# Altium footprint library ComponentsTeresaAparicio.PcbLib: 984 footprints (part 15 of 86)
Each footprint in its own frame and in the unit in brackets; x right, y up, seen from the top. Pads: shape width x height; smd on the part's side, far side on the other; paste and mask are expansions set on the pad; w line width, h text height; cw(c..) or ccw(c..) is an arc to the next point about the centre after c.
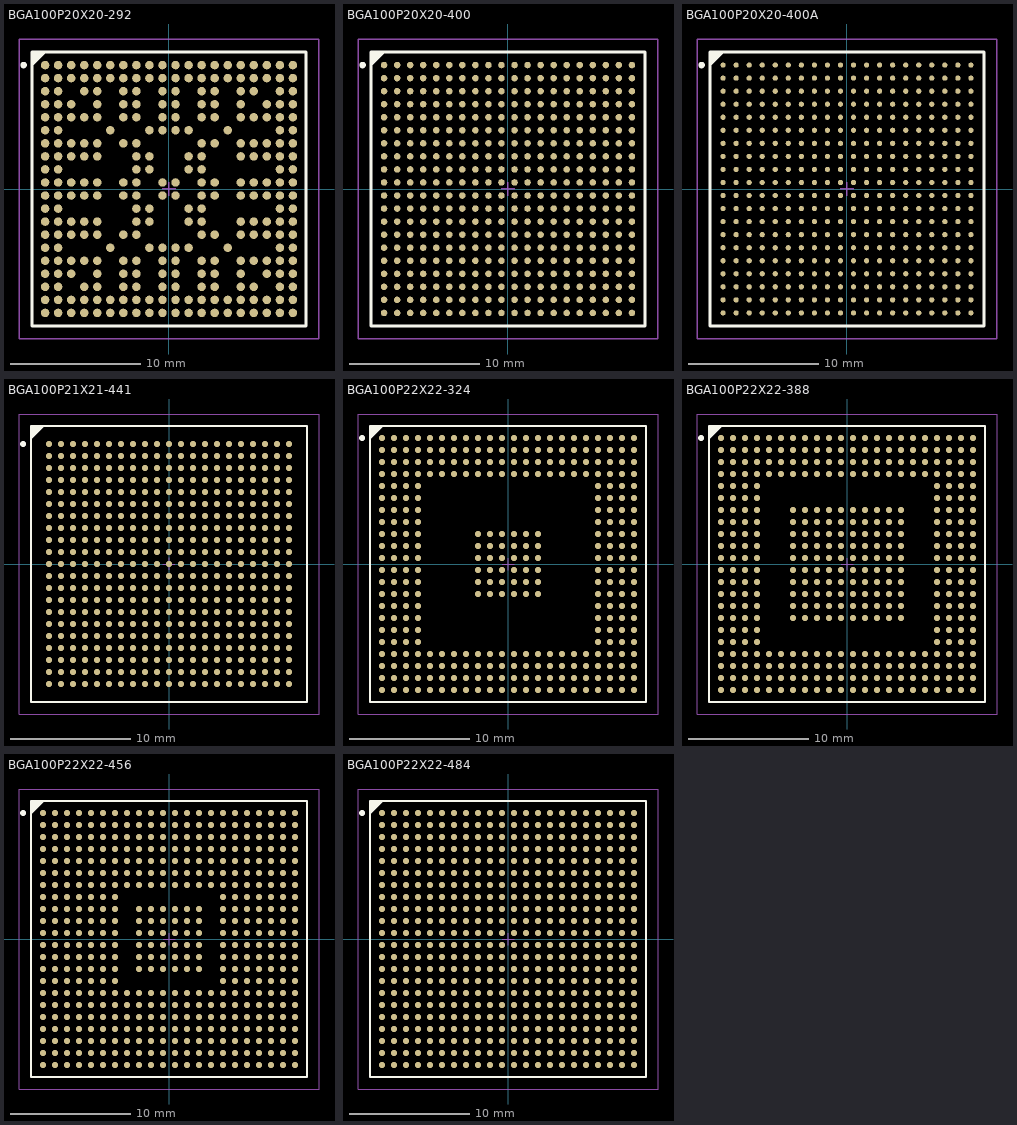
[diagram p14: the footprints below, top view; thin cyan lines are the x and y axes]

## BGA100P20X20-292 [mm] "BGA, 292-Leads, Body 21x21mm, Pitch 1mm"
height 3.09
pads (292):
  round 0.65 smd: A1(-9.5,9.5) A2(-8.5,9.5) A3(-7.5,9.5) A4(-6.5,9.5) A5(-5.5,9.5) A6(-4.5,9.5) A7(-3.5,9.5) A8(-2.5,9.5) A9(-1.5,9.5) A10(-0.5,9.5) A11(0.5,9.5) A12(1.5,9.5) A13(2.5,9.5) A14(3.5,9.5) A15(4.5,9.5) A16(5.5,9.5) A17(6.5,9.5) A18(7.5,9.5) A19(8.5,9.5) A20(9.5,9.5) B1(-9.5,8.5) B2(-8.5,8.5) B3(-7.5,8.5) B4(-6.5,8.5) B5(-5.5,8.5) B6(-4.5,8.5) B7(-3.5,8.5) B8(-2.5,8.5) B9(-1.5,8.5) B10(-0.5,8.5) B11(0.5,8.5) B12(1.5,8.5) B13(2.5,8.5) B14(3.5,8.5) B15(4.5,8.5) B16(5.5,8.5) B17(6.5,8.5) B18(7.5,8.5) B19(8.5,8.5) B20(9.5,8.5) C1(-9.5,7.5) C2(-8.5,7.5) C4(-6.5,7.5) C5(-5.5,7.5) C7(-3.5,7.5) C8(-2.5,7.5) C10(-0.5,7.5) C11(0.5,7.5) C13(2.5,7.5) C14(3.5,7.5) C16(5.5,7.5) C17(6.5,7.5) C19(8.5,7.5) C20(9.5,7.5) D1(-9.5,6.5) D2(-8.5,6.5) D3(-7.5,6.5) D5(-5.5,6.5) D7(-3.5,6.5) D8(-2.5,6.5) D10(-0.5,6.5) D11(0.5,6.5) D13(2.5,6.5) D14(3.5,6.5) D16(5.5,6.5) D18(7.5,6.5) D19(8.5,6.5) D20(9.5,6.5) E1(-9.5,5.5) E2(-8.5,5.5) E3(-7.5,5.5) E4(-6.5,5.5) E5(-5.5,5.5) E7(-3.5,5.5) E8(-2.5,5.5) E10(-0.5,5.5) E11(0.5,5.5) E13(2.5,5.5) E14(3.5,5.5) E16(5.5,5.5) E17(6.5,5.5) E18(7.5,5.5) E19(8.5,5.5) E20(9.5,5.5) F1(-9.5,4.5) F2(-8.5,4.5) F6(-4.5,4.5) F9(-1.5,4.5) F10(-0.5,4.5) F11(0.5,4.5) F12(1.5,4.5) F15(4.5,4.5) F19(8.5,4.5) F20(9.5,4.5) G1(-9.5,3.5) G2(-8.5,3.5) G3(-7.5,3.5) G4(-6.5,3.5) G5(-5.5,3.5) G7(-3.5,3.5) G8(-2.5,3.5) G13(2.5,3.5) G14(3.5,3.5) G16(5.5,3.5) G17(6.5,3.5) G18(7.5,3.5) G19(8.5,3.5) G20(9.5,3.5) H1(-9.5,2.5) H2(-8.5,2.5) H3(-7.5,2.5) H4(-6.5,2.5) H5(-5.5,2.5) H8(-2.5,2.5) H9(-1.5,2.5) H12(1.5,2.5) H13(2.5,2.5) H16(5.5,2.5) H17(6.5,2.5) H18(7.5,2.5) H19(8.5,2.5) H20(9.5,2.5) J1(-9.5,1.5) J2(-8.5,1.5) J8(-2.5,1.5) J9(-1.5,1.5) J12(1.5,1.5) J13(2.5,1.5) J19(8.5,1.5) J20(9.5,1.5) K1(-9.5,0.5) K2(-8.5,0.5) K3(-7.5,0.5) K4(-6.5,0.5) K5(-5.5,0.5) K7(-3.5,0.5) K8(-2.5,0.5) K10(-0.5,0.5) K11(0.5,0.5) K13(2.5,0.5) K14(3.5,0.5) K16(5.5,0.5) K17(6.5,0.5) K18(7.5,0.5) K19(8.5,0.5) K20(9.5,0.5) L1(-9.5,-0.5) L2(-8.5,-0.5) L3(-7.5,-0.5) L4(-6.5,-0.5) L5(-5.5,-0.5) L7(-3.5,-0.5) L8(-2.5,-0.5) L10(-0.5,-0.5) L11(0.5,-0.5) L13(2.5,-0.5) L14(3.5,-0.5) L16(5.5,-0.5) L17(6.5,-0.5) L18(7.5,-0.5) L19(8.5,-0.5) L20(9.5,-0.5) M1(-9.5,-1.5) M2(-8.5,-1.5) M8(-2.5,-1.5) M9(-1.5,-1.5) M12(1.5,-1.5) M13(2.5,-1.5) M19(8.5,-1.5) M20(9.5,-1.5) N1(-9.5,-2.5) N2(-8.5,-2.5) N3(-7.5,-2.5) N4(-6.5,-2.5) N5(-5.5,-2.5) N8(-2.5,-2.5) N9(-1.5,-2.5) N12(1.5,-2.5) N13(2.5,-2.5) N16(5.5,-2.5) N17(6.5,-2.5) N18(7.5,-2.5) N19(8.5,-2.5) N20(9.5,-2.5) P1(-9.5,-3.5) P2(-8.5,-3.5) P3(-7.5,-3.5) P4(-6.5,-3.5) P5(-5.5,-3.5) P7(-3.5,-3.5) P8(-2.5,-3.5) P13(2.5,-3.5) P14(3.5,-3.5) P16(5.5,-3.5) P17(6.5,-3.5) P18(7.5,-3.5) P19(8.5,-3.5) P20(9.5,-3.5) R1(-9.5,-4.5) R2(-8.5,-4.5) R6(-4.5,-4.5) R9(-1.5,-4.5) R10(-0.5,-4.5) R11(0.5,-4.5) R12(1.5,-4.5) R15(4.5,-4.5) R19(8.5,-4.5) R20(9.5,-4.5) T1(-9.5,-5.5) T2(-8.5,-5.5) T3(-7.5,-5.5) T4(-6.5,-5.5) T5(-5.5,-5.5) T7(-3.5,-5.5) T8(-2.5,-5.5) T10(-0.5,-5.5) T11(0.5,-5.5) T13(2.5,-5.5) T14(3.5,-5.5) T16(5.5,-5.5) T17(6.5,-5.5) T18(7.5,-5.5) T19(8.5,-5.5) T20(9.5,-5.5) U1(-9.5,-6.5) U2(-8.5,-6.5) U3(-7.5,-6.5) U5(-5.5,-6.5) U7(-3.5,-6.5) U8(-2.5,-6.5) U10(-0.5,-6.5) U11(0.5,-6.5) U13(2.5,-6.5) U14(3.5,-6.5) U16(5.5,-6.5) U18(7.5,-6.5) U19(8.5,-6.5) U20(9.5,-6.5) V1(-9.5,-7.5) V2(-8.5,-7.5) V4(-6.5,-7.5) V5(-5.5,-7.5) V7(-3.5,-7.5) V8(-2.5,-7.5) V10(-0.5,-7.5) V11(0.5,-7.5) V13(2.5,-7.5) V14(3.5,-7.5) V16(5.5,-7.5) V17(6.5,-7.5) V19(8.5,-7.5) V20(9.5,-7.5) W1(-9.5,-8.5) W2(-8.5,-8.5) W3(-7.5,-8.5) W4(-6.5,-8.5) W5(-5.5,-8.5) W6(-4.5,-8.5) W7(-3.5,-8.5) W8(-2.5,-8.5) W9(-1.5,-8.5) W10(-0.5,-8.5) W11(0.5,-8.5) W12(1.5,-8.5) W13(2.5,-8.5) W14(3.5,-8.5) W15(4.5,-8.5) W16(5.5,-8.5) W17(6.5,-8.5) W18(7.5,-8.5) W19(8.5,-8.5) W20(9.5,-8.5) Y1(-9.5,-9.5) Y2(-8.5,-9.5) Y3(-7.5,-9.5) Y4(-6.5,-9.5) Y5(-5.5,-9.5) Y6(-4.5,-9.5) Y7(-3.5,-9.5) Y8(-2.5,-9.5) Y9(-1.5,-9.5) Y10(-0.5,-9.5) Y11(0.5,-9.5) Y12(1.5,-9.5) Y13(2.5,-9.5) Y14(3.5,-9.5) Y15(4.5,-9.5) Y16(5.5,-9.5) Y17(6.5,-9.5) Y18(7.5,-9.5) Y19(8.5,-9.5) Y20(9.5,-9.5)
Top Overlay:
  circle w0.25: c-11.15,9.5 r0.125
  region: -9.525,10.5 -10.5,9.525 -10.5,10.5
  lines w0.2: -10.5,9.525 -9.525,10.5 ; -10.5,-10.5 10.5,-10.5 10.5,10.5 -10.5,10.5 -10.5,-10.5
Mechanical 13:
  lines w0.1: -10.5,-10.5 10.5,-10.5 10.5,10.5 -10.5,10.5 -10.5,-10.5
Mechanical 15:
  lines w0.1: -0.5,0 0.5,0 ; 0,-0.5 0,0.5 ; -11.5,-11.5 11.5,-11.5 11.5,11.5 -11.5,11.5 -11.5,-11.5
3D body: height 0, standoff 0, extent -10.5,-10.5 10.5,10.5

## BGA100P20X20-400 [mm] "BGA, 400-Leads, Body 21x21mm, Pitch 1mm"
height 2.2
pads (400):
  round 0.5 smd: A1(-9.5,9.5) A2(-8.5,9.5) A3(-7.5,9.5) A4(-6.5,9.5) A5(-5.5,9.5) A6(-4.5,9.5) A7(-3.5,9.5) A8(-2.5,9.5) A9(-1.5,9.5) A10(-0.5,9.5) A11(0.5,9.5) A12(1.5,9.5) A13(2.5,9.5) A14(3.5,9.5) A15(4.5,9.5) A16(5.5,9.5) A17(6.5,9.5) A18(7.5,9.5) A19(8.5,9.5) A20(9.5,9.5) B1(-9.5,8.5) B2(-8.5,8.5) B3(-7.5,8.5) B4(-6.5,8.5) B5(-5.5,8.5) B6(-4.5,8.5) B7(-3.5,8.5) B8(-2.5,8.5) B9(-1.5,8.5) B10(-0.5,8.5) B11(0.5,8.5) B12(1.5,8.5) B13(2.5,8.5) B14(3.5,8.5) B15(4.5,8.5) B16(5.5,8.5) B17(6.5,8.5) B18(7.5,8.5) B19(8.5,8.5) B20(9.5,8.5) C1(-9.5,7.5) C2(-8.5,7.5) C3(-7.5,7.5) C4(-6.5,7.5) C5(-5.5,7.5) C6(-4.5,7.5) C7(-3.5,7.5) C8(-2.5,7.5) C9(-1.5,7.5) C10(-0.5,7.5) C11(0.5,7.5) C12(1.5,7.5) C13(2.5,7.5) C14(3.5,7.5) C15(4.5,7.5) C16(5.5,7.5) C17(6.5,7.5) C18(7.5,7.5) C19(8.5,7.5) C20(9.5,7.5) D1(-9.5,6.5) D2(-8.5,6.5) D3(-7.5,6.5) D4(-6.5,6.5) D5(-5.5,6.5) D6(-4.5,6.5) D7(-3.5,6.5) D8(-2.5,6.5) D9(-1.5,6.5) D10(-0.5,6.5) D11(0.5,6.5) D12(1.5,6.5) D13(2.5,6.5) D14(3.5,6.5) D15(4.5,6.5) D16(5.5,6.5) D17(6.5,6.5) D18(7.5,6.5) D19(8.5,6.5) D20(9.5,6.5) E1(-9.5,5.5) E2(-8.5,5.5) E3(-7.5,5.5) E4(-6.5,5.5) E5(-5.5,5.5) E6(-4.5,5.5) E7(-3.5,5.5) E8(-2.5,5.5) E9(-1.5,5.5) E10(-0.5,5.5) E11(0.5,5.5) E12(1.5,5.5) E13(2.5,5.5) E14(3.5,5.5) E15(4.5,5.5) E16(5.5,5.5) E17(6.5,5.5) E18(7.5,5.5) E19(8.5,5.5) E20(9.5,5.5) F1(-9.5,4.5) F2(-8.5,4.5) F3(-7.5,4.5) F4(-6.5,4.5) F5(-5.5,4.5) F6(-4.5,4.5) F7(-3.5,4.5) F8(-2.5,4.5) F9(-1.5,4.5) F10(-0.5,4.5) F11(0.5,4.5) F12(1.5,4.5) F13(2.5,4.5) F14(3.5,4.5) F15(4.5,4.5) F16(5.5,4.5) F17(6.5,4.5) F18(7.5,4.5) F19(8.5,4.5) F20(9.5,4.5) G1(-9.5,3.5) G2(-8.5,3.5) G3(-7.5,3.5) G4(-6.5,3.5) G5(-5.5,3.5) G6(-4.5,3.5) G7(-3.5,3.5) G8(-2.5,3.5) G9(-1.5,3.5) G10(-0.5,3.5) G11(0.5,3.5) G12(1.5,3.5) G13(2.5,3.5) G14(3.5,3.5) G15(4.5,3.5) G16(5.5,3.5) G17(6.5,3.5) G18(7.5,3.5) G19(8.5,3.5) G20(9.5,3.5) H1(-9.5,2.5) H2(-8.5,2.5) H3(-7.5,2.5) H4(-6.5,2.5) H5(-5.5,2.5) H6(-4.5,2.5) H7(-3.5,2.5) H8(-2.5,2.5) H9(-1.5,2.5) H10(-0.5,2.5) H11(0.5,2.5) H12(1.5,2.5) H13(2.5,2.5) H14(3.5,2.5) H15(4.5,2.5) H16(5.5,2.5) H17(6.5,2.5) H18(7.5,2.5) H19(8.5,2.5) H20(9.5,2.5) J1(-9.5,1.5) J2(-8.5,1.5) J3(-7.5,1.5) J4(-6.5,1.5) J5(-5.5,1.5) J6(-4.5,1.5) J7(-3.5,1.5) J8(-2.5,1.5) J9(-1.5,1.5) J10(-0.5,1.5) J11(0.5,1.5) J12(1.5,1.5) J13(2.5,1.5) J14(3.5,1.5) J15(4.5,1.5) J16(5.5,1.5) J17(6.5,1.5) J18(7.5,1.5) J19(8.5,1.5) J20(9.5,1.5) K1(-9.5,0.5) K2(-8.5,0.5) K3(-7.5,0.5) K4(-6.5,0.5) K5(-5.5,0.5) K6(-4.5,0.5) K7(-3.5,0.5) K8(-2.5,0.5) K9(-1.5,0.5) K10(-0.5,0.5) K11(0.5,0.5) K12(1.5,0.5) K13(2.5,0.5) K14(3.5,0.5) K15(4.5,0.5) K16(5.5,0.5) K17(6.5,0.5) K18(7.5,0.5) K19(8.5,0.5) K20(9.5,0.5) L1(-9.5,-0.5) L2(-8.5,-0.5) L3(-7.5,-0.5) L4(-6.5,-0.5) L5(-5.5,-0.5) L6(-4.5,-0.5) L7(-3.5,-0.5) L8(-2.5,-0.5) L9(-1.5,-0.5) L10(-0.5,-0.5) L11(0.5,-0.5) L12(1.5,-0.5) L13(2.5,-0.5) L14(3.5,-0.5) L15(4.5,-0.5) L16(5.5,-0.5) L17(6.5,-0.5) L18(7.5,-0.5) L19(8.5,-0.5) L20(9.5,-0.5) M1(-9.5,-1.5) M2(-8.5,-1.5) M3(-7.5,-1.5) M4(-6.5,-1.5) M5(-5.5,-1.5) M6(-4.5,-1.5) M7(-3.5,-1.5) M8(-2.5,-1.5) M9(-1.5,-1.5) M10(-0.5,-1.5) M11(0.5,-1.5) M12(1.5,-1.5) M13(2.5,-1.5) M14(3.5,-1.5) M15(4.5,-1.5) M16(5.5,-1.5) M17(6.5,-1.5) M18(7.5,-1.5) M19(8.5,-1.5) M20(9.5,-1.5) N1(-9.5,-2.5) N2(-8.5,-2.5) N3(-7.5,-2.5) N4(-6.5,-2.5) N5(-5.5,-2.5) N6(-4.5,-2.5) N7(-3.5,-2.5) N8(-2.5,-2.5) N9(-1.5,-2.5) N10(-0.5,-2.5) N11(0.5,-2.5) N12(1.5,-2.5) N13(2.5,-2.5) N14(3.5,-2.5) N15(4.5,-2.5) N16(5.5,-2.5) N17(6.5,-2.5) N18(7.5,-2.5) N19(8.5,-2.5) N20(9.5,-2.5) P1(-9.5,-3.5) P2(-8.5,-3.5) P3(-7.5,-3.5) P4(-6.5,-3.5) P5(-5.5,-3.5) P6(-4.5,-3.5) P7(-3.5,-3.5) P8(-2.5,-3.5) P9(-1.5,-3.5) P10(-0.5,-3.5) P11(0.5,-3.5) P12(1.5,-3.5) P13(2.5,-3.5) P14(3.5,-3.5) P15(4.5,-3.5) P16(5.5,-3.5) P17(6.5,-3.5) P18(7.5,-3.5) P19(8.5,-3.5) P20(9.5,-3.5) R1(-9.5,-4.5) R2(-8.5,-4.5) R3(-7.5,-4.5) R4(-6.5,-4.5) R5(-5.5,-4.5) R6(-4.5,-4.5) R7(-3.5,-4.5) R8(-2.5,-4.5) R9(-1.5,-4.5) R10(-0.5,-4.5) R11(0.5,-4.5) R12(1.5,-4.5) R13(2.5,-4.5) R14(3.5,-4.5) R15(4.5,-4.5) R16(5.5,-4.5) R17(6.5,-4.5) R18(7.5,-4.5) R19(8.5,-4.5) R20(9.5,-4.5) T1(-9.5,-5.5) T2(-8.5,-5.5) T3(-7.5,-5.5) T4(-6.5,-5.5) T5(-5.5,-5.5) T6(-4.5,-5.5) T7(-3.5,-5.5) T8(-2.5,-5.5) T9(-1.5,-5.5) T10(-0.5,-5.5) T11(0.5,-5.5) T12(1.5,-5.5) T13(2.5,-5.5) T14(3.5,-5.5) T15(4.5,-5.5) T16(5.5,-5.5) T17(6.5,-5.5) T18(7.5,-5.5) T19(8.5,-5.5) T20(9.5,-5.5) U1(-9.5,-6.5) U2(-8.5,-6.5) U3(-7.5,-6.5) U4(-6.5,-6.5) U5(-5.5,-6.5) U6(-4.5,-6.5) U7(-3.5,-6.5) U8(-2.5,-6.5) U9(-1.5,-6.5) U10(-0.5,-6.5) U11(0.5,-6.5) U12(1.5,-6.5) U13(2.5,-6.5) U14(3.5,-6.5) U15(4.5,-6.5) U16(5.5,-6.5) U17(6.5,-6.5) U18(7.5,-6.5) U19(8.5,-6.5) U20(9.5,-6.5) V1(-9.5,-7.5) V2(-8.5,-7.5) V3(-7.5,-7.5) V4(-6.5,-7.5) V5(-5.5,-7.5) V6(-4.5,-7.5) V7(-3.5,-7.5) V8(-2.5,-7.5) V9(-1.5,-7.5) V10(-0.5,-7.5) V11(0.5,-7.5) V12(1.5,-7.5) V13(2.5,-7.5) V14(3.5,-7.5) V15(4.5,-7.5) V16(5.5,-7.5) V17(6.5,-7.5) V18(7.5,-7.5) V19(8.5,-7.5) V20(9.5,-7.5) W1(-9.5,-8.5) W2(-8.5,-8.5) W3(-7.5,-8.5) W4(-6.5,-8.5) W5(-5.5,-8.5) W6(-4.5,-8.5) W7(-3.5,-8.5) W8(-2.5,-8.5) W9(-1.5,-8.5) W10(-0.5,-8.5) W11(0.5,-8.5) W12(1.5,-8.5) W13(2.5,-8.5) W14(3.5,-8.5) W15(4.5,-8.5) W16(5.5,-8.5) W17(6.5,-8.5) W18(7.5,-8.5) W19(8.5,-8.5) W20(9.5,-8.5) Y1(-9.5,-9.5) Y2(-8.5,-9.5) Y3(-7.5,-9.5) Y4(-6.5,-9.5) Y5(-5.5,-9.5) Y6(-4.5,-9.5) Y7(-3.5,-9.5) Y8(-2.5,-9.5) Y9(-1.5,-9.5) Y10(-0.5,-9.5) Y11(0.5,-9.5) Y12(1.5,-9.5) Y13(2.5,-9.5) Y14(3.5,-9.5) Y15(4.5,-9.5) Y16(5.5,-9.5) Y17(6.5,-9.5) Y18(7.5,-9.5) Y19(8.5,-9.5) Y20(9.5,-9.5)
Top Overlay:
  circle w0.25: c-11.15,9.5 r0.125
  region: -9.5,10.5 -10.5,9.5 -10.5,10.5
  lines w0.2: -10.5,9.5 -9.5,10.5 ; -10.5,-10.5 -10.5,10.5 10.5,10.5 10.5,-10.5 -10.5,-10.5
Mechanical 13:
  lines w0.1: -10.5,-10.5 -10.5,10.5 10.5,10.5 10.5,-10.5 -10.5,-10.5
Mechanical 15:
  lines w0.1: -0.5,0 0.5,0 ; 0,-0.5 0,0.5 ; -11.5,-11.5 -11.5,11.5 11.5,11.5 11.5,-11.5 -11.5,-11.5
3D body: height 0, standoff 0, extent -10.5,-10.5 10.5,10.5

## BGA100P20X20-400A [mm] "BGA, 400-Leads, Body 21x21mm, Pitch 1mm"
height 1.4
pads (400):
  round 0.4 smd: A1(-9.5,9.5) A2(-8.5,9.5) A3(-7.5,9.5) A4(-6.5,9.5) A5(-5.5,9.5) A6(-4.5,9.5) A7(-3.5,9.5) A8(-2.5,9.5) A9(-1.5,9.5) A10(-0.5,9.5) A11(0.5,9.5) A12(1.5,9.5) A13(2.5,9.5) A14(3.5,9.5) A15(4.5,9.5) A16(5.5,9.5) A17(6.5,9.5) A18(7.5,9.5) A19(8.5,9.5) A20(9.5,9.5) B1(-9.5,8.5) B2(-8.5,8.5) B3(-7.5,8.5) B4(-6.5,8.5) B5(-5.5,8.5) B6(-4.5,8.5) B7(-3.5,8.5) B8(-2.5,8.5) B9(-1.5,8.5) B10(-0.5,8.5) B11(0.5,8.5) B12(1.5,8.5) B13(2.5,8.5) B14(3.5,8.5) B15(4.5,8.5) B16(5.5,8.5) B17(6.5,8.5) B18(7.5,8.5) B19(8.5,8.5) B20(9.5,8.5) C1(-9.5,7.5) C2(-8.5,7.5) C3(-7.5,7.5) C4(-6.5,7.5) C5(-5.5,7.5) C6(-4.5,7.5) C7(-3.5,7.5) C8(-2.5,7.5) C9(-1.5,7.5) C10(-0.5,7.5) C11(0.5,7.5) C12(1.5,7.5) C13(2.5,7.5) C14(3.5,7.5) C15(4.5,7.5) C16(5.5,7.5) C17(6.5,7.5) C18(7.5,7.5) C19(8.5,7.5) C20(9.5,7.5) D1(-9.5,6.5) D2(-8.5,6.5) D3(-7.5,6.5) D4(-6.5,6.5) D5(-5.5,6.5) D6(-4.5,6.5) D7(-3.5,6.5) D8(-2.5,6.5) D9(-1.5,6.5) D10(-0.5,6.5) D11(0.5,6.5) D12(1.5,6.5) D13(2.5,6.5) D14(3.5,6.5) D15(4.5,6.5) D16(5.5,6.5) D17(6.5,6.5) D18(7.5,6.5) D19(8.5,6.5) D20(9.5,6.5) E1(-9.5,5.5) E2(-8.5,5.5) E3(-7.5,5.5) E4(-6.5,5.5) E5(-5.5,5.5) E6(-4.5,5.5) E7(-3.5,5.5) E8(-2.5,5.5) E9(-1.5,5.5) E10(-0.5,5.5) E11(0.5,5.5) E12(1.5,5.5) E13(2.5,5.5) E14(3.5,5.5) E15(4.5,5.5) E16(5.5,5.5) E17(6.5,5.5) E18(7.5,5.5) E19(8.5,5.5) E20(9.5,5.5) F1(-9.5,4.5) F2(-8.5,4.5) F3(-7.5,4.5) F4(-6.5,4.5) F5(-5.5,4.5) F6(-4.5,4.5) F7(-3.5,4.5) F8(-2.5,4.5) F9(-1.5,4.5) F10(-0.5,4.5) F11(0.5,4.5) F12(1.5,4.5) F13(2.5,4.5) F14(3.5,4.5) F15(4.5,4.5) F16(5.5,4.5) F17(6.5,4.5) F18(7.5,4.5) F19(8.5,4.5) F20(9.5,4.5) G1(-9.5,3.5) G2(-8.5,3.5) G3(-7.5,3.5) G4(-6.5,3.5) G5(-5.5,3.5) G6(-4.5,3.5) G7(-3.5,3.5) G8(-2.5,3.5) G9(-1.5,3.5) G10(-0.5,3.5) G11(0.5,3.5) G12(1.5,3.5) G13(2.5,3.5) G14(3.5,3.5) G15(4.5,3.5) G16(5.5,3.5) G17(6.5,3.5) G18(7.5,3.5) G19(8.5,3.5) G20(9.5,3.5) H1(-9.5,2.5) H2(-8.5,2.5) H3(-7.5,2.5) H4(-6.5,2.5) H5(-5.5,2.5) H6(-4.5,2.5) H7(-3.5,2.5) H8(-2.5,2.5) H9(-1.5,2.5) H10(-0.5,2.5) H11(0.5,2.5) H12(1.5,2.5) H13(2.5,2.5) H14(3.5,2.5) H15(4.5,2.5) H16(5.5,2.5) H17(6.5,2.5) H18(7.5,2.5) H19(8.5,2.5) H20(9.5,2.5) J1(-9.5,1.5) J2(-8.5,1.5) J3(-7.5,1.5) J4(-6.5,1.5) J5(-5.5,1.5) J6(-4.5,1.5) J7(-3.5,1.5) J8(-2.5,1.5) J9(-1.5,1.5) J10(-0.5,1.5) J11(0.5,1.5) J12(1.5,1.5) J13(2.5,1.5) J14(3.5,1.5) J15(4.5,1.5) J16(5.5,1.5) J17(6.5,1.5) J18(7.5,1.5) J19(8.5,1.5) J20(9.5,1.5) K1(-9.5,0.5) K2(-8.5,0.5) K3(-7.5,0.5) K4(-6.5,0.5) K5(-5.5,0.5) K6(-4.5,0.5) K7(-3.5,0.5) K8(-2.5,0.5) K9(-1.5,0.5) K10(-0.5,0.5) K11(0.5,0.5) K12(1.5,0.5) K13(2.5,0.5) K14(3.5,0.5) K15(4.5,0.5) K16(5.5,0.5) K17(6.5,0.5) K18(7.5,0.5) K19(8.5,0.5) K20(9.5,0.5) L1(-9.5,-0.5) L2(-8.5,-0.5) L3(-7.5,-0.5) L4(-6.5,-0.5) L5(-5.5,-0.5) L6(-4.5,-0.5) L7(-3.5,-0.5) L8(-2.5,-0.5) L9(-1.5,-0.5) L10(-0.5,-0.5) L11(0.5,-0.5) L12(1.5,-0.5) L13(2.5,-0.5) L14(3.5,-0.5) L15(4.5,-0.5) L16(5.5,-0.5) L17(6.5,-0.5) L18(7.5,-0.5) L19(8.5,-0.5) L20(9.5,-0.5) M1(-9.5,-1.5) M2(-8.5,-1.5) M3(-7.5,-1.5) M4(-6.5,-1.5) M5(-5.5,-1.5) M6(-4.5,-1.5) M7(-3.5,-1.5) M8(-2.5,-1.5) M9(-1.5,-1.5) M10(-0.5,-1.5) M11(0.5,-1.5) M12(1.5,-1.5) M13(2.5,-1.5) M14(3.5,-1.5) M15(4.5,-1.5) M16(5.5,-1.5) M17(6.5,-1.5) M18(7.5,-1.5) M19(8.5,-1.5) M20(9.5,-1.5) N1(-9.5,-2.5) N2(-8.5,-2.5) N3(-7.5,-2.5) N4(-6.5,-2.5) N5(-5.5,-2.5) N6(-4.5,-2.5) N7(-3.5,-2.5) N8(-2.5,-2.5) N9(-1.5,-2.5) N10(-0.5,-2.5) N11(0.5,-2.5) N12(1.5,-2.5) N13(2.5,-2.5) N14(3.5,-2.5) N15(4.5,-2.5) N16(5.5,-2.5) N17(6.5,-2.5) N18(7.5,-2.5) N19(8.5,-2.5) N20(9.5,-2.5) P1(-9.5,-3.5) P2(-8.5,-3.5) P3(-7.5,-3.5) P4(-6.5,-3.5) P5(-5.5,-3.5) P6(-4.5,-3.5) P7(-3.5,-3.5) P8(-2.5,-3.5) P9(-1.5,-3.5) P10(-0.5,-3.5) P11(0.5,-3.5) P12(1.5,-3.5) P13(2.5,-3.5) P14(3.5,-3.5) P15(4.5,-3.5) P16(5.5,-3.5) P17(6.5,-3.5) P18(7.5,-3.5) P19(8.5,-3.5) P20(9.5,-3.5) R1(-9.5,-4.5) R2(-8.5,-4.5) R3(-7.5,-4.5) R4(-6.5,-4.5) R5(-5.5,-4.5) R6(-4.5,-4.5) R7(-3.5,-4.5) R8(-2.5,-4.5) R9(-1.5,-4.5) R10(-0.5,-4.5) R11(0.5,-4.5) R12(1.5,-4.5) R13(2.5,-4.5) R14(3.5,-4.5) R15(4.5,-4.5) R16(5.5,-4.5) R17(6.5,-4.5) R18(7.5,-4.5) R19(8.5,-4.5) R20(9.5,-4.5) T1(-9.5,-5.5) T2(-8.5,-5.5) T3(-7.5,-5.5) T4(-6.5,-5.5) T5(-5.5,-5.5) T6(-4.5,-5.5) T7(-3.5,-5.5) T8(-2.5,-5.5) T9(-1.5,-5.5) T10(-0.5,-5.5) T11(0.5,-5.5) T12(1.5,-5.5) T13(2.5,-5.5) T14(3.5,-5.5) T15(4.5,-5.5) T16(5.5,-5.5) T17(6.5,-5.5) T18(7.5,-5.5) T19(8.5,-5.5) T20(9.5,-5.5) U1(-9.5,-6.5) U2(-8.5,-6.5) U3(-7.5,-6.5) U4(-6.5,-6.5) U5(-5.5,-6.5) U6(-4.5,-6.5) U7(-3.5,-6.5) U8(-2.5,-6.5) U9(-1.5,-6.5) U10(-0.5,-6.5) U11(0.5,-6.5) U12(1.5,-6.5) U13(2.5,-6.5) U14(3.5,-6.5) U15(4.5,-6.5) U16(5.5,-6.5) U17(6.5,-6.5) U18(7.5,-6.5) U19(8.5,-6.5) U20(9.5,-6.5) V1(-9.5,-7.5) V2(-8.5,-7.5) V3(-7.5,-7.5) V4(-6.5,-7.5) V5(-5.5,-7.5) V6(-4.5,-7.5) V7(-3.5,-7.5) V8(-2.5,-7.5) V9(-1.5,-7.5) V10(-0.5,-7.5) V11(0.5,-7.5) V12(1.5,-7.5) V13(2.5,-7.5) V14(3.5,-7.5) V15(4.5,-7.5) V16(5.5,-7.5) V17(6.5,-7.5) V18(7.5,-7.5) V19(8.5,-7.5) V20(9.5,-7.5) W1(-9.5,-8.5) W2(-8.5,-8.5) W3(-7.5,-8.5) W4(-6.5,-8.5) W5(-5.5,-8.5) W6(-4.5,-8.5) W7(-3.5,-8.5) W8(-2.5,-8.5) W9(-1.5,-8.5) W10(-0.5,-8.5) W11(0.5,-8.5) W12(1.5,-8.5) W13(2.5,-8.5) W14(3.5,-8.5) W15(4.5,-8.5) W16(5.5,-8.5) W17(6.5,-8.5) W18(7.5,-8.5) W19(8.5,-8.5) W20(9.5,-8.5) Y1(-9.5,-9.5) Y2(-8.5,-9.5) Y3(-7.5,-9.5) Y4(-6.5,-9.5) Y5(-5.5,-9.5) Y6(-4.5,-9.5) Y7(-3.5,-9.5) Y8(-2.5,-9.5) Y9(-1.5,-9.5) Y10(-0.5,-9.5) Y11(0.5,-9.5) Y12(1.5,-9.5) Y13(2.5,-9.5) Y14(3.5,-9.5) Y15(4.5,-9.5) Y16(5.5,-9.5) Y17(6.5,-9.5) Y18(7.5,-9.5) Y19(8.5,-9.5) Y20(9.5,-9.5)
Top Overlay:
  circle w0.25: c-11.15,9.5 r0.125
  region: -9.5,10.5 -10.5,9.5 -10.5,10.5
  lines w0.2: -10.5,9.5 -9.5,10.5 ; -10.5,-10.5 -10.5,10.5 10.5,10.5 10.5,-10.5 -10.5,-10.5
Mechanical 13:
  lines w0.1: -10.5,-10.5 -10.5,10.5 10.5,10.5 10.5,-10.5 -10.5,-10.5
Mechanical 15:
  lines w0.1: -0.5,0 0.5,0 ; 0,-0.5 0,0.5 ; -11.5,-11.5 -11.5,11.5 11.5,11.5 11.5,-11.5 -11.5,-11.5
3D body: height 0, standoff 0, extent -10.5,-10.5 10.5,10.5

## BGA100P21X21-441 [mm] "BGA, 441-Leads, Body 23x23mm, Pitch 1mm"
height 3.5
pads (441):
  round 0.5 smd: A1(-10,10) A2(-9,10) A3(-8,10) A4(-7,10) A5(-6,10) A6(-5,10) A7(-4,10) A8(-3,10) A9(-2,10) A10(-1,10) A11(0,10) A12(1,10) A13(2,10) A14(3,10) A15(4,10) A16(5,10) A17(6,10) A18(7,10) A19(8,10) A20(9,10) A21(10,10) AA1(-10,-10) AA2(-9,-10) AA3(-8,-10) AA4(-7,-10) AA5(-6,-10) AA6(-5,-10) AA7(-4,-10) AA8(-3,-10) AA9(-2,-10) AA10(-1,-10) AA11(0,-10) AA12(1,-10) AA13(2,-10) AA14(3,-10) AA15(4,-10) AA16(5,-10) AA17(6,-10) AA18(7,-10) AA19(8,-10) AA20(9,-10) AA21(10,-10) B1(-10,9) B2(-9,9) B3(-8,9) B4(-7,9) B5(-6,9) B6(-5,9) B7(-4,9) B8(-3,9) B9(-2,9) B10(-1,9) B11(0,9) B12(1,9) B13(2,9) B14(3,9) B15(4,9) B16(5,9) B17(6,9) B18(7,9) B19(8,9) B20(9,9) B21(10,9) C1(-10,8) C2(-9,8) C3(-8,8) C4(-7,8) C5(-6,8) C6(-5,8) C7(-4,8) C8(-3,8) C9(-2,8) C10(-1,8) C11(0,8) C12(1,8) C13(2,8) C14(3,8) C15(4,8) C16(5,8) C17(6,8) C18(7,8) C19(8,8) C20(9,8) C21(10,8) D1(-10,7) D2(-9,7) D3(-8,7) D4(-7,7) D5(-6,7) D6(-5,7) D7(-4,7) D8(-3,7) D9(-2,7) D10(-1,7) D11(0,7) D12(1,7) D13(2,7) D14(3,7) D15(4,7) D16(5,7) D17(6,7) D18(7,7) D19(8,7) D20(9,7) D21(10,7) E1(-10,6) E2(-9,6) E3(-8,6) E4(-7,6) E5(-6,6) E6(-5,6) E7(-4,6) E8(-3,6) E9(-2,6) E10(-1,6) E11(0,6) E12(1,6) E13(2,6) E14(3,6) E15(4,6) E16(5,6) E17(6,6) E18(7,6) E19(8,6) E20(9,6) E21(10,6) F1(-10,5) F2(-9,5) F3(-8,5) F4(-7,5) F5(-6,5) F6(-5,5) F7(-4,5) F8(-3,5) F9(-2,5) F10(-1,5) F11(0,5) F12(1,5) F13(2,5) F14(3,5) F15(4,5) F16(5,5) F17(6,5) F18(7,5) F19(8,5) F20(9,5) F21(10,5) G1(-10,4) G2(-9,4) G3(-8,4) G4(-7,4) G5(-6,4) G6(-5,4) G7(-4,4) G8(-3,4) G9(-2,4) G10(-1,4) G11(0,4) G12(1,4) G13(2,4) G14(3,4) G15(4,4) G16(5,4) G17(6,4) G18(7,4) G19(8,4) G20(9,4) G21(10,4) H1(-10,3) H2(-9,3) H3(-8,3) H4(-7,3) H5(-6,3) H6(-5,3) H7(-4,3) H8(-3,3) H9(-2,3) H10(-1,3) H11(0,3) H12(1,3) H13(2,3) H14(3,3) H15(4,3) H16(5,3) H17(6,3) H18(7,3) H19(8,3) H20(9,3) H21(10,3) J1(-10,2) J2(-9,2) J3(-8,2) J4(-7,2) J5(-6,2) J6(-5,2) J7(-4,2) J8(-3,2) J9(-2,2) J10(-1,2) J11(0,2) J12(1,2) J13(2,2) J14(3,2) J15(4,2) J16(5,2) J17(6,2) J18(7,2) J19(8,2) J20(9,2) J21(10,2) K1(-10,1) K2(-9,1) K3(-8,1) K4(-7,1) K5(-6,1) K6(-5,1) K7(-4,1) K8(-3,1) K9(-2,1) K10(-1,1) K11(0,1) K12(1,1) K13(2,1) K14(3,1) K15(4,1) K16(5,1) K17(6,1) K18(7,1) K19(8,1) K20(9,1) K21(10,1) L1(-10,0) L2(-9,0) L3(-8,0) L4(-7,0) L5(-6,0) L6(-5,0) L7(-4,0) L8(-3,0) L9(-2,0) L10(-1,0) L11(0,0) L12(1,0) L13(2,0) L14(3,0) L15(4,0) L16(5,0) L17(6,0) L18(7,0) L19(8,0) L20(9,0) L21(10,0) M1(-10,-1) M2(-9,-1) M3(-8,-1) M4(-7,-1) M5(-6,-1) M6(-5,-1) M7(-4,-1) M8(-3,-1) M9(-2,-1) M10(-1,-1) M11(0,-1) M12(1,-1) M13(2,-1) M14(3,-1) M15(4,-1) M16(5,-1) M17(6,-1) M18(7,-1) M19(8,-1) M20(9,-1) M21(10,-1) N1(-10,-2) N2(-9,-2) N3(-8,-2) N4(-7,-2) N5(-6,-2) N6(-5,-2) N7(-4,-2) N8(-3,-2) N9(-2,-2) N10(-1,-2) N11(0,-2) N12(1,-2) N13(2,-2) N14(3,-2) N15(4,-2) N16(5,-2) N17(6,-2) N18(7,-2) N19(8,-2) N20(9,-2) N21(10,-2) P1(-10,-3) P2(-9,-3) P3(-8,-3) P4(-7,-3) P5(-6,-3) P6(-5,-3) P7(-4,-3) P8(-3,-3) P9(-2,-3) P10(-1,-3) P11(0,-3) P12(1,-3) P13(2,-3) P14(3,-3) P15(4,-3) P16(5,-3) P17(6,-3) P18(7,-3) P19(8,-3) P20(9,-3) P21(10,-3) R1(-10,-4) R2(-9,-4) R3(-8,-4) R4(-7,-4) R5(-6,-4) R6(-5,-4) R7(-4,-4) R8(-3,-4) R9(-2,-4) R10(-1,-4) R11(0,-4) R12(1,-4) R13(2,-4) R14(3,-4) R15(4,-4) R16(5,-4) R17(6,-4) R18(7,-4) R19(8,-4) R20(9,-4) R21(10,-4) T1(-10,-5) T2(-9,-5) T3(-8,-5) T4(-7,-5) T5(-6,-5) T6(-5,-5) T7(-4,-5) T8(-3,-5) T9(-2,-5) T10(-1,-5) T11(0,-5) T12(1,-5) T13(2,-5) T14(3,-5) T15(4,-5) T16(5,-5) T17(6,-5) T18(7,-5) T19(8,-5) T20(9,-5) T21(10,-5) U1(-10,-6) U2(-9,-6) U3(-8,-6) U4(-7,-6) U5(-6,-6) U6(-5,-6) U7(-4,-6) U8(-3,-6) U9(-2,-6) U10(-1,-6) U11(0,-6) U12(1,-6) U13(2,-6) U14(3,-6) U15(4,-6) U16(5,-6) U17(6,-6) U18(7,-6) U19(8,-6) U20(9,-6) U21(10,-6) V1(-10,-7) V2(-9,-7) V3(-8,-7) V4(-7,-7) V5(-6,-7) V6(-5,-7) V7(-4,-7) V8(-3,-7) V9(-2,-7) V10(-1,-7) V11(0,-7) V12(1,-7) V13(2,-7) V14(3,-7) V15(4,-7) V16(5,-7) V17(6,-7) V18(7,-7) V19(8,-7) V20(9,-7) V21(10,-7) W1(-10,-8) W2(-9,-8) W3(-8,-8) W4(-7,-8) W5(-6,-8) W6(-5,-8) W7(-4,-8) W8(-3,-8) W9(-2,-8) W10(-1,-8) W11(0,-8) W12(1,-8) W13(2,-8) W14(3,-8) W15(4,-8) W16(5,-8) W17(6,-8) W18(7,-8) W19(8,-8) W20(9,-8) W21(10,-8) Y1(-10,-9) Y2(-9,-9) Y3(-8,-9) Y4(-7,-9) Y5(-6,-9) Y6(-5,-9) Y7(-4,-9) Y8(-3,-9) Y9(-2,-9) Y10(-1,-9) Y11(0,-9) Y12(1,-9) Y13(2,-9) Y14(3,-9) Y15(4,-9) Y16(5,-9) Y17(6,-9) Y18(7,-9) Y19(8,-9) Y20(9,-9) Y21(10,-9)
Top Overlay:
  circle w0.25: c-12.15,10 r0.125
  region: -10.5,11.5 -11.5,10.5 -11.5,11.5
  lines w0.2: -11.5,10.5 -10.5,11.5 ; -11.5,-11.5 11.5,-11.5 11.5,11.5 -11.5,11.5 -11.5,-11.5
Mechanical 13:
  lines w0.1: -11.5,-11.5 11.5,-11.5 11.5,11.5 -11.5,11.5 -11.5,-11.5
Mechanical 15:
  lines w0.1: -0.5,0 0.5,0 ; 0,-0.5 0,0.5 ; -12.5,-12.5 12.5,-12.5 12.5,12.5 -12.5,12.5 -12.5,-12.5
3D body: height 0, standoff 0, extent -11.5,-11.5 11.5,11.5

## BGA100P22X22-324 [mm] "BGA, 324-Leads, Body 23x23mm, Pitch 1mm"
height 3
pads (324):
  round 0.5 smd: A1(-10.5,10.5) A2(-9.5,10.5) A3(-8.5,10.5) A4(-7.5,10.5) A5(-6.5,10.5) A6(-5.5,10.5) A7(-4.5,10.5) A8(-3.5,10.5) A9(-2.5,10.5) A10(-1.5,10.5) A11(-0.5,10.5) A12(0.5,10.5) A13(1.5,10.5) A14(2.5,10.5) A15(3.5,10.5) A16(4.5,10.5) A17(5.5,10.5) A18(6.5,10.5) A19(7.5,10.5) A20(8.5,10.5) A21(9.5,10.5) A22(10.5,10.5) AA1(-10.5,-9.5) AA2(-9.5,-9.5) AA3(-8.5,-9.5) AA4(-7.5,-9.5) AA5(-6.5,-9.5) AA6(-5.5,-9.5) AA7(-4.5,-9.5) AA8(-3.5,-9.5) AA9(-2.5,-9.5) AA10(-1.5,-9.5) AA11(-0.5,-9.5) AA12(0.5,-9.5) AA13(1.5,-9.5) AA14(2.5,-9.5) AA15(3.5,-9.5) AA16(4.5,-9.5) AA17(5.5,-9.5) AA18(6.5,-9.5) AA19(7.5,-9.5) AA20(8.5,-9.5) AA21(9.5,-9.5) AA22(10.5,-9.5) AB1(-10.5,-10.5) AB2(-9.5,-10.5) AB3(-8.5,-10.5) AB4(-7.5,-10.5) AB5(-6.5,-10.5) AB6(-5.5,-10.5) AB7(-4.5,-10.5) AB8(-3.5,-10.5) AB9(-2.5,-10.5) AB10(-1.5,-10.5) AB11(-0.5,-10.5) AB12(0.5,-10.5) AB13(1.5,-10.5) AB14(2.5,-10.5) AB15(3.5,-10.5) AB16(4.5,-10.5) AB17(5.5,-10.5) AB18(6.5,-10.5) AB19(7.5,-10.5) AB20(8.5,-10.5) AB21(9.5,-10.5) AB22(10.5,-10.5) B1(-10.5,9.5) B2(-9.5,9.5) B3(-8.5,9.5) B4(-7.5,9.5) B5(-6.5,9.5) B6(-5.5,9.5) B7(-4.5,9.5) B8(-3.5,9.5) B9(-2.5,9.5) B10(-1.5,9.5) B11(-0.5,9.5) B12(0.5,9.5) B13(1.5,9.5) B14(2.5,9.5) B15(3.5,9.5) B16(4.5,9.5) B17(5.5,9.5) B18(6.5,9.5) B19(7.5,9.5) B20(8.5,9.5) B21(9.5,9.5) B22(10.5,9.5) C1(-10.5,8.5) C2(-9.5,8.5) C3(-8.5,8.5) C4(-7.5,8.5) C5(-6.5,8.5) C6(-5.5,8.5) C7(-4.5,8.5) C8(-3.5,8.5) C9(-2.5,8.5) C10(-1.5,8.5) C11(-0.5,8.5) C12(0.5,8.5) C13(1.5,8.5) C14(2.5,8.5) C15(3.5,8.5) C16(4.5,8.5) C17(5.5,8.5) C18(6.5,8.5) C19(7.5,8.5) C20(8.5,8.5) C21(9.5,8.5) C22(10.5,8.5) D1(-10.5,7.5) D2(-9.5,7.5) D3(-8.5,7.5) D4(-7.5,7.5) D5(-6.5,7.5) D6(-5.5,7.5) D7(-4.5,7.5) D8(-3.5,7.5) D9(-2.5,7.5) D10(-1.5,7.5) D11(-0.5,7.5) D12(0.5,7.5) D13(1.5,7.5) D14(2.5,7.5) D15(3.5,7.5) D16(4.5,7.5) D17(5.5,7.5) D18(6.5,7.5) D19(7.5,7.5) D20(8.5,7.5) D21(9.5,7.5) D22(10.5,7.5) E1(-10.5,6.5) E2(-9.5,6.5) E3(-8.5,6.5) E4(-7.5,6.5) E19(7.5,6.5) E20(8.5,6.5) E21(9.5,6.5) E22(10.5,6.5) F1(-10.5,5.5) F2(-9.5,5.5) F3(-8.5,5.5) F4(-7.5,5.5) F19(7.5,5.5) F20(8.5,5.5) F21(9.5,5.5) F22(10.5,5.5) G1(-10.5,4.5) G2(-9.5,4.5) G3(-8.5,4.5) G4(-7.5,4.5) G19(7.5,4.5) G20(8.5,4.5) G21(9.5,4.5) G22(10.5,4.5) H1(-10.5,3.5) H2(-9.5,3.5) H3(-8.5,3.5) H4(-7.5,3.5) H19(7.5,3.5) H20(8.5,3.5) H21(9.5,3.5) H22(10.5,3.5) J1(-10.5,2.5) J2(-9.5,2.5) J3(-8.5,2.5) J4(-7.5,2.5) J9(-2.5,2.5) J10(-1.5,2.5) J11(-0.5,2.5) J12(0.5,2.5) J13(1.5,2.5) J14(2.5,2.5) J19(7.5,2.5) J20(8.5,2.5) J21(9.5,2.5) J22(10.5,2.5) K1(-10.5,1.5) K2(-9.5,1.5) K3(-8.5,1.5) K4(-7.5,1.5) K9(-2.5,1.5) K10(-1.5,1.5) K11(-0.5,1.5) K12(0.5,1.5) K13(1.5,1.5) K14(2.5,1.5) K19(7.5,1.5) K20(8.5,1.5) K21(9.5,1.5) K22(10.5,1.5) L1(-10.5,0.5) L2(-9.5,0.5) L3(-8.5,0.5) L4(-7.5,0.5) L9(-2.5,0.5) L10(-1.5,0.5) L11(-0.5,0.5) L12(0.5,0.5) L13(1.5,0.5) L14(2.5,0.5) L19(7.5,0.5) L20(8.5,0.5) L21(9.5,0.5) L22(10.5,0.5) M1(-10.5,-0.5) M2(-9.5,-0.5) M3(-8.5,-0.5) M4(-7.5,-0.5) M9(-2.5,-0.5) M10(-1.5,-0.5) M11(-0.5,-0.5) M12(0.5,-0.5) M13(1.5,-0.5) M14(2.5,-0.5) M19(7.5,-0.5) M20(8.5,-0.5) M21(9.5,-0.5) M22(10.5,-0.5) N1(-10.5,-1.5) N2(-9.5,-1.5) N3(-8.5,-1.5) N4(-7.5,-1.5) N9(-2.5,-1.5) N10(-1.5,-1.5) N11(-0.5,-1.5) N12(0.5,-1.5) N13(1.5,-1.5) N14(2.5,-1.5) N19(7.5,-1.5) N20(8.5,-1.5) N21(9.5,-1.5) N22(10.5,-1.5) P1(-10.5,-2.5) P2(-9.5,-2.5) P3(-8.5,-2.5) P4(-7.5,-2.5) P9(-2.5,-2.5) P10(-1.5,-2.5) P11(-0.5,-2.5) P12(0.5,-2.5) P13(1.5,-2.5) P14(2.5,-2.5) P19(7.5,-2.5) P20(8.5,-2.5) P21(9.5,-2.5) P22(10.5,-2.5) R1(-10.5,-3.5) R2(-9.5,-3.5) R3(-8.5,-3.5) R4(-7.5,-3.5) R19(7.5,-3.5) R20(8.5,-3.5) R21(9.5,-3.5) R22(10.5,-3.5) T1(-10.5,-4.5) T2(-9.5,-4.5) T3(-8.5,-4.5) T4(-7.5,-4.5) T19(7.5,-4.5) T20(8.5,-4.5) T21(9.5,-4.5) T22(10.5,-4.5) U1(-10.5,-5.5) U2(-9.5,-5.5) U3(-8.5,-5.5) U4(-7.5,-5.5) U19(7.5,-5.5) U20(8.5,-5.5) U21(9.5,-5.5) U22(10.5,-5.5) V1(-10.5,-6.5) V2(-9.5,-6.5) V3(-8.5,-6.5) V4(-7.5,-6.5) V19(7.5,-6.5) V20(8.5,-6.5) V21(9.5,-6.5) V22(10.5,-6.5) W1(-10.5,-7.5) W2(-9.5,-7.5) W3(-8.5,-7.5) W4(-7.5,-7.5) W5(-6.5,-7.5) W6(-5.5,-7.5) W7(-4.5,-7.5) W8(-3.5,-7.5) W9(-2.5,-7.5) W10(-1.5,-7.5) W11(-0.5,-7.5) W12(0.5,-7.5) W13(1.5,-7.5) W14(2.5,-7.5) W15(3.5,-7.5) W16(4.5,-7.5) W17(5.5,-7.5) W18(6.5,-7.5) W19(7.5,-7.5) W20(8.5,-7.5) W21(9.5,-7.5) W22(10.5,-7.5) Y1(-10.5,-8.5) Y2(-9.5,-8.5) Y3(-8.5,-8.5) Y4(-7.5,-8.5) Y5(-6.5,-8.5) Y6(-5.5,-8.5) Y7(-4.5,-8.5) Y8(-3.5,-8.5) Y9(-2.5,-8.5) Y10(-1.5,-8.5) Y11(-0.5,-8.5) Y12(0.5,-8.5) Y13(1.5,-8.5) Y14(2.5,-8.5) Y15(3.5,-8.5) Y16(4.5,-8.5) Y17(5.5,-8.5) Y18(6.5,-8.5) Y19(7.5,-8.5) Y20(8.5,-8.5) Y21(9.5,-8.5) Y22(10.5,-8.5)
Top Overlay:
  circle w0.25: c-12.15,10.5 r0.125
  region: -10.5,11.5 -11.5,10.5 -11.5,11.5
  lines w0.2: -11.5,10.5 -10.5,11.5 ; -11.5,-11.5 11.5,-11.5 11.5,11.5 -11.5,11.5 -11.5,-11.5
Mechanical 13:
  lines w0.1: -11.5,-11.5 11.5,-11.5 11.5,11.5 -11.5,11.5 -11.5,-11.5
Mechanical 15:
  lines w0.1: -0.5,0 0.5,0 ; 0,-0.5 0,0.5 ; -12.5,-12.5 12.5,-12.5 12.5,12.5 -12.5,12.5 -12.5,-12.5
3D body: height 0, standoff 0, extent -11.5,-11.5 11.5,11.5

## BGA100P22X22-388 [mm] "BGA, 388-Leads, Body 23x23mm, Pitch 1mm"
height 2.6
pads (388):
  round 0.5 smd: A1(-10.5,10.5) A2(-9.5,10.5) A3(-8.5,10.5) A4(-7.5,10.5) A5(-6.5,10.5) A6(-5.5,10.5) A7(-4.5,10.5) A8(-3.5,10.5) A9(-2.5,10.5) A10(-1.5,10.5) A11(-0.5,10.5) A12(0.5,10.5) A13(1.5,10.5) A14(2.5,10.5) A15(3.5,10.5) A16(4.5,10.5) A17(5.5,10.5) A18(6.5,10.5) A19(7.5,10.5) A20(8.5,10.5) A21(9.5,10.5) A22(10.5,10.5) AA1(-10.5,-9.5) AA2(-9.5,-9.5) AA3(-8.5,-9.5) AA4(-7.5,-9.5) AA5(-6.5,-9.5) AA6(-5.5,-9.5) AA7(-4.5,-9.5) AA8(-3.5,-9.5) AA9(-2.5,-9.5) AA10(-1.5,-9.5) AA11(-0.5,-9.5) AA12(0.5,-9.5) AA13(1.5,-9.5) AA14(2.5,-9.5) AA15(3.5,-9.5) AA16(4.5,-9.5) AA17(5.5,-9.5) AA18(6.5,-9.5) AA19(7.5,-9.5) AA20(8.5,-9.5) AA21(9.5,-9.5) AA22(10.5,-9.5) AB1(-10.5,-10.5) AB2(-9.5,-10.5) AB3(-8.5,-10.5) AB4(-7.5,-10.5) AB5(-6.5,-10.5) AB6(-5.5,-10.5) AB7(-4.5,-10.5) AB8(-3.5,-10.5) AB9(-2.5,-10.5) AB10(-1.5,-10.5) AB11(-0.5,-10.5) AB12(0.5,-10.5) AB13(1.5,-10.5) AB14(2.5,-10.5) AB15(3.5,-10.5) AB16(4.5,-10.5) AB17(5.5,-10.5) AB18(6.5,-10.5) AB19(7.5,-10.5) AB20(8.5,-10.5) AB21(9.5,-10.5) AB22(10.5,-10.5) B1(-10.5,9.5) B2(-9.5,9.5) B3(-8.5,9.5) B4(-7.5,9.5) B5(-6.5,9.5) B6(-5.5,9.5) B7(-4.5,9.5) B8(-3.5,9.5) B9(-2.5,9.5) B10(-1.5,9.5) B11(-0.5,9.5) B12(0.5,9.5) B13(1.5,9.5) B14(2.5,9.5) B15(3.5,9.5) B16(4.5,9.5) B17(5.5,9.5) B18(6.5,9.5) B19(7.5,9.5) B20(8.5,9.5) B21(9.5,9.5) B22(10.5,9.5) C1(-10.5,8.5) C2(-9.5,8.5) C3(-8.5,8.5) C4(-7.5,8.5) C5(-6.5,8.5) C6(-5.5,8.5) C7(-4.5,8.5) C8(-3.5,8.5) C9(-2.5,8.5) C10(-1.5,8.5) C11(-0.5,8.5) C12(0.5,8.5) C13(1.5,8.5) C14(2.5,8.5) C15(3.5,8.5) C16(4.5,8.5) C17(5.5,8.5) C18(6.5,8.5) C19(7.5,8.5) C20(8.5,8.5) C21(9.5,8.5) C22(10.5,8.5) D1(-10.5,7.5) D2(-9.5,7.5) D3(-8.5,7.5) D4(-7.5,7.5) D5(-6.5,7.5) D6(-5.5,7.5) D7(-4.5,7.5) D8(-3.5,7.5) D9(-2.5,7.5) D10(-1.5,7.5) D11(-0.5,7.5) D12(0.5,7.5) D13(1.5,7.5) D14(2.5,7.5) D15(3.5,7.5) D16(4.5,7.5) D17(5.5,7.5) D18(6.5,7.5) D19(7.5,7.5) D20(8.5,7.5) D21(9.5,7.5) D22(10.5,7.5) E1(-10.5,6.5) E2(-9.5,6.5) E3(-8.5,6.5) E4(-7.5,6.5) E19(7.5,6.5) E20(8.5,6.5) E21(9.5,6.5) E22(10.5,6.5) F1(-10.5,5.5) F2(-9.5,5.5) F3(-8.5,5.5) F4(-7.5,5.5) F19(7.5,5.5) F20(8.5,5.5) F21(9.5,5.5) F22(10.5,5.5) G1(-10.5,4.5) G2(-9.5,4.5) G3(-8.5,4.5) G4(-7.5,4.5) G7(-4.5,4.5) G8(-3.5,4.5) G9(-2.5,4.5) G10(-1.5,4.5) G11(-0.5,4.5) G12(0.5,4.5) G13(1.5,4.5) G14(2.5,4.5) G15(3.5,4.5) G16(4.5,4.5) G19(7.5,4.5) G20(8.5,4.5) G21(9.5,4.5) G22(10.5,4.5) H1(-10.5,3.5) H2(-9.5,3.5) H3(-8.5,3.5) H4(-7.5,3.5) H7(-4.5,3.5) H8(-3.5,3.5) H9(-2.5,3.5) H10(-1.5,3.5) H11(-0.5,3.5) H12(0.5,3.5) H13(1.5,3.5) H14(2.5,3.5) H15(3.5,3.5) H16(4.5,3.5) H19(7.5,3.5) H20(8.5,3.5) H21(9.5,3.5) H22(10.5,3.5) J1(-10.5,2.5) J2(-9.5,2.5) J3(-8.5,2.5) J4(-7.5,2.5) J7(-4.5,2.5) J8(-3.5,2.5) J9(-2.5,2.5) J10(-1.5,2.5) J11(-0.5,2.5) J12(0.5,2.5) J13(1.5,2.5) J14(2.5,2.5) J15(3.5,2.5) J16(4.5,2.5) J19(7.5,2.5) J20(8.5,2.5) J21(9.5,2.5) J22(10.5,2.5) K1(-10.5,1.5) K2(-9.5,1.5) K3(-8.5,1.5) K4(-7.5,1.5) K7(-4.5,1.5) K8(-3.5,1.5) K9(-2.5,1.5) K10(-1.5,1.5) K11(-0.5,1.5) K12(0.5,1.5) K13(1.5,1.5) K14(2.5,1.5) K15(3.5,1.5) K16(4.5,1.5) K19(7.5,1.5) K20(8.5,1.5) K21(9.5,1.5) K22(10.5,1.5) L1(-10.5,0.5) L2(-9.5,0.5) L3(-8.5,0.5) L4(-7.5,0.5) L7(-4.5,0.5) L8(-3.5,0.5) L9(-2.5,0.5) L10(-1.5,0.5) L11(-0.5,0.5) L12(0.5,0.5) L13(1.5,0.5) L14(2.5,0.5) L15(3.5,0.5) L16(4.5,0.5) L19(7.5,0.5) L20(8.5,0.5) L21(9.5,0.5) L22(10.5,0.5) M1(-10.5,-0.5) M2(-9.5,-0.5) M3(-8.5,-0.5) M4(-7.5,-0.5) M7(-4.5,-0.5) M8(-3.5,-0.5) M9(-2.5,-0.5) M10(-1.5,-0.5) M11(-0.5,-0.5) M12(0.5,-0.5) M13(1.5,-0.5) M14(2.5,-0.5) M15(3.5,-0.5) M16(4.5,-0.5) M19(7.5,-0.5) M20(8.5,-0.5) M21(9.5,-0.5) M22(10.5,-0.5) N1(-10.5,-1.5) N2(-9.5,-1.5) N3(-8.5,-1.5) N4(-7.5,-1.5) N7(-4.5,-1.5) N8(-3.5,-1.5) N9(-2.5,-1.5) N10(-1.5,-1.5) N11(-0.5,-1.5) N12(0.5,-1.5) N13(1.5,-1.5) N14(2.5,-1.5) N15(3.5,-1.5) N16(4.5,-1.5) N19(7.5,-1.5) N20(8.5,-1.5) N21(9.5,-1.5) N22(10.5,-1.5) P1(-10.5,-2.5) P2(-9.5,-2.5) P3(-8.5,-2.5) P4(-7.5,-2.5) P7(-4.5,-2.5) P8(-3.5,-2.5) P9(-2.5,-2.5) P10(-1.5,-2.5) P11(-0.5,-2.5) P12(0.5,-2.5) P13(1.5,-2.5) P14(2.5,-2.5) P15(3.5,-2.5) P16(4.5,-2.5) P19(7.5,-2.5) P20(8.5,-2.5) P21(9.5,-2.5) P22(10.5,-2.5) R1(-10.5,-3.5) R2(-9.5,-3.5) R3(-8.5,-3.5) R4(-7.5,-3.5) R7(-4.5,-3.5) R8(-3.5,-3.5) R9(-2.5,-3.5) R10(-1.5,-3.5) R11(-0.5,-3.5) R12(0.5,-3.5) R13(1.5,-3.5) R14(2.5,-3.5) R15(3.5,-3.5) R16(4.5,-3.5) R19(7.5,-3.5) R20(8.5,-3.5) R21(9.5,-3.5) R22(10.5,-3.5) T1(-10.5,-4.5) T2(-9.5,-4.5) T3(-8.5,-4.5) T4(-7.5,-4.5) T7(-4.5,-4.5) T8(-3.5,-4.5) T9(-2.5,-4.5) T10(-1.5,-4.5) T11(-0.5,-4.5) T12(0.5,-4.5) T13(1.5,-4.5) T14(2.5,-4.5) T15(3.5,-4.5) T16(4.5,-4.5) T19(7.5,-4.5) T20(8.5,-4.5) T21(9.5,-4.5) T22(10.5,-4.5) U1(-10.5,-5.5) U2(-9.5,-5.5) U3(-8.5,-5.5) U4(-7.5,-5.5) U19(7.5,-5.5) U20(8.5,-5.5) U21(9.5,-5.5) U22(10.5,-5.5) V1(-10.5,-6.5) V2(-9.5,-6.5) V3(-8.5,-6.5) V4(-7.5,-6.5) V19(7.5,-6.5) V20(8.5,-6.5) V21(9.5,-6.5) V22(10.5,-6.5) W1(-10.5,-7.5) W2(-9.5,-7.5) W3(-8.5,-7.5) W4(-7.5,-7.5) W5(-6.5,-7.5) W6(-5.5,-7.5) W7(-4.5,-7.5) W8(-3.5,-7.5) W9(-2.5,-7.5) W10(-1.5,-7.5) W11(-0.5,-7.5) W12(0.5,-7.5) W13(1.5,-7.5) W14(2.5,-7.5) W15(3.5,-7.5) W16(4.5,-7.5) W17(5.5,-7.5) W18(6.5,-7.5) W19(7.5,-7.5) W20(8.5,-7.5) W21(9.5,-7.5) W22(10.5,-7.5) Y1(-10.5,-8.5) Y2(-9.5,-8.5) Y3(-8.5,-8.5) Y4(-7.5,-8.5) Y5(-6.5,-8.5) Y6(-5.5,-8.5) Y7(-4.5,-8.5) Y8(-3.5,-8.5) Y9(-2.5,-8.5) Y10(-1.5,-8.5) Y11(-0.5,-8.5) Y12(0.5,-8.5) Y13(1.5,-8.5) Y14(2.5,-8.5) Y15(3.5,-8.5) Y16(4.5,-8.5) Y17(5.5,-8.5) Y18(6.5,-8.5) Y19(7.5,-8.5) Y20(8.5,-8.5) Y21(9.5,-8.5) Y22(10.5,-8.5)
Top Overlay:
  circle w0.25: c-12.15,10.5 r0.125
  region: -10.5,11.5 -11.5,10.5 -11.5,11.5
  lines w0.2: -11.5,10.5 -10.5,11.5 ; -11.5,-11.5 11.5,-11.5 11.5,11.5 -11.5,11.5 -11.5,-11.5
Mechanical 13:
  lines w0.1: -11.5,-11.5 11.5,-11.5 11.5,11.5 -11.5,11.5 -11.5,-11.5
Mechanical 15:
  lines w0.1: -0.5,0 0.5,0 ; 0,-0.5 0,0.5 ; -12.5,-12.5 12.5,-12.5 12.5,12.5 -12.5,12.5 -12.5,-12.5
3D body: height 0, standoff 0, extent -11.5,-11.5 11.5,11.5

## BGA100P22X22-456 [mm] "456-Ball Fine Pitch Ball Grid Array (FG456)"
height 2.6
pads (456):
  round 0.5 smd: A1(-10.5,10.5) A2(-9.5,10.5) A3(-8.5,10.5) A4(-7.5,10.5) A5(-6.5,10.5) A6(-5.5,10.5) A7(-4.5,10.5) A8(-3.5,10.5) A9(-2.5,10.5) A10(-1.5,10.5) A11(-0.5,10.5) A12(0.5,10.5) A13(1.5,10.5) A14(2.5,10.5) A15(3.5,10.5) A16(4.5,10.5) A17(5.5,10.5) A18(6.5,10.5) A19(7.5,10.5) A20(8.5,10.5) A21(9.5,10.5) A22(10.5,10.5) AA1(-10.5,-9.5) AA2(-9.5,-9.5) AA3(-8.5,-9.5) AA4(-7.5,-9.5) AA5(-6.5,-9.5) AA6(-5.5,-9.5) AA7(-4.5,-9.5) AA8(-3.5,-9.5) AA9(-2.5,-9.5) AA10(-1.5,-9.5) AA11(-0.5,-9.5) AA12(0.5,-9.5) AA13(1.5,-9.5) AA14(2.5,-9.5) AA15(3.5,-9.5) AA16(4.5,-9.5) AA17(5.5,-9.5) AA18(6.5,-9.5) AA19(7.5,-9.5) AA20(8.5,-9.5) AA21(9.5,-9.5) AA22(10.5,-9.5) AB1(-10.5,-10.5) AB2(-9.5,-10.5) AB3(-8.5,-10.5) AB4(-7.5,-10.5) AB5(-6.5,-10.5) AB6(-5.5,-10.5) AB7(-4.5,-10.5) AB8(-3.5,-10.5) AB9(-2.5,-10.5) AB10(-1.5,-10.5) AB11(-0.5,-10.5) AB12(0.5,-10.5) AB13(1.5,-10.5) AB14(2.5,-10.5) AB15(3.5,-10.5) AB16(4.5,-10.5) AB17(5.5,-10.5) AB18(6.5,-10.5) AB19(7.5,-10.5) AB20(8.5,-10.5) AB21(9.5,-10.5) AB22(10.5,-10.5) B1(-10.5,9.5) B2(-9.5,9.5) B3(-8.5,9.5) B4(-7.5,9.5) B5(-6.5,9.5) B6(-5.5,9.5) B7(-4.5,9.5) B8(-3.5,9.5) B9(-2.5,9.5) B10(-1.5,9.5) B11(-0.5,9.5) B12(0.5,9.5) B13(1.5,9.5) B14(2.5,9.5) B15(3.5,9.5) B16(4.5,9.5) B17(5.5,9.5) B18(6.5,9.5) B19(7.5,9.5) B20(8.5,9.5) B21(9.5,9.5) B22(10.5,9.5) C1(-10.5,8.5) C2(-9.5,8.5) C3(-8.5,8.5) C4(-7.5,8.5) C5(-6.5,8.5) C6(-5.5,8.5) C7(-4.5,8.5) C8(-3.5,8.5) C9(-2.5,8.5) C10(-1.5,8.5) C11(-0.5,8.5) C12(0.5,8.5) C13(1.5,8.5) C14(2.5,8.5) C15(3.5,8.5) C16(4.5,8.5) C17(5.5,8.5) C18(6.5,8.5) C19(7.5,8.5) C20(8.5,8.5) C21(9.5,8.5) C22(10.5,8.5) D1(-10.5,7.5) D2(-9.5,7.5) D3(-8.5,7.5) D4(-7.5,7.5) D5(-6.5,7.5) D6(-5.5,7.5) D7(-4.5,7.5) D8(-3.5,7.5) D9(-2.5,7.5) D10(-1.5,7.5) D11(-0.5,7.5) D12(0.5,7.5) D13(1.5,7.5) D14(2.5,7.5) D15(3.5,7.5) D16(4.5,7.5) D17(5.5,7.5) D18(6.5,7.5) D19(7.5,7.5) D20(8.5,7.5) D21(9.5,7.5) D22(10.5,7.5) E1(-10.5,6.5) E2(-9.5,6.5) E3(-8.5,6.5) E4(-7.5,6.5) E5(-6.5,6.5) E6(-5.5,6.5) E7(-4.5,6.5) E8(-3.5,6.5) E9(-2.5,6.5) E10(-1.5,6.5) E11(-0.5,6.5) E12(0.5,6.5) E13(1.5,6.5) E14(2.5,6.5) E15(3.5,6.5) E16(4.5,6.5) E17(5.5,6.5) E18(6.5,6.5) E19(7.5,6.5) E20(8.5,6.5) E21(9.5,6.5) E22(10.5,6.5) F1(-10.5,5.5) F2(-9.5,5.5) F3(-8.5,5.5) F4(-7.5,5.5) F5(-6.5,5.5) F6(-5.5,5.5) F7(-4.5,5.5) F8(-3.5,5.5) F9(-2.5,5.5) F10(-1.5,5.5) F11(-0.5,5.5) F12(0.5,5.5) F13(1.5,5.5) F14(2.5,5.5) F15(3.5,5.5) F16(4.5,5.5) F17(5.5,5.5) F18(6.5,5.5) F19(7.5,5.5) F20(8.5,5.5) F21(9.5,5.5) F22(10.5,5.5) G1(-10.5,4.5) G2(-9.5,4.5) G3(-8.5,4.5) G4(-7.5,4.5) G5(-6.5,4.5) G6(-5.5,4.5) G7(-4.5,4.5) G8(-3.5,4.5) G9(-2.5,4.5) G10(-1.5,4.5) G11(-0.5,4.5) G12(0.5,4.5) G13(1.5,4.5) G14(2.5,4.5) G15(3.5,4.5) G16(4.5,4.5) G17(5.5,4.5) G18(6.5,4.5) G19(7.5,4.5) G20(8.5,4.5) G21(9.5,4.5) G22(10.5,4.5) H1(-10.5,3.5) H2(-9.5,3.5) H3(-8.5,3.5) H4(-7.5,3.5) H5(-6.5,3.5) H6(-5.5,3.5) H7(-4.5,3.5) H16(4.5,3.5) H17(5.5,3.5) H18(6.5,3.5) H19(7.5,3.5) H20(8.5,3.5) H21(9.5,3.5) H22(10.5,3.5) J1(-10.5,2.5) J2(-9.5,2.5) J3(-8.5,2.5) J4(-7.5,2.5) J5(-6.5,2.5) J6(-5.5,2.5) J7(-4.5,2.5) J9(-2.5,2.5) J10(-1.5,2.5) J11(-0.5,2.5) J12(0.5,2.5) J13(1.5,2.5) J14(2.5,2.5) J16(4.5,2.5) J17(5.5,2.5) J18(6.5,2.5) J19(7.5,2.5) J20(8.5,2.5) J21(9.5,2.5) J22(10.5,2.5) K1(-10.5,1.5) K2(-9.5,1.5) K3(-8.5,1.5) K4(-7.5,1.5) K5(-6.5,1.5) K6(-5.5,1.5) K7(-4.5,1.5) K9(-2.5,1.5) K10(-1.5,1.5) K11(-0.5,1.5) K12(0.5,1.5) K13(1.5,1.5) K14(2.5,1.5) K16(4.5,1.5) K17(5.5,1.5) K18(6.5,1.5) K19(7.5,1.5) K20(8.5,1.5) K21(9.5,1.5) K22(10.5,1.5) L1(-10.5,0.5) L2(-9.5,0.5) L3(-8.5,0.5) L4(-7.5,0.5) L5(-6.5,0.5) L6(-5.5,0.5) L7(-4.5,0.5) L9(-2.5,0.5) L10(-1.5,0.5) L11(-0.5,0.5) L12(0.5,0.5) L13(1.5,0.5) L14(2.5,0.5) L16(4.5,0.5) L17(5.5,0.5) L18(6.5,0.5) L19(7.5,0.5) L20(8.5,0.5) L21(9.5,0.5) L22(10.5,0.5) M1(-10.5,-0.5) M2(-9.5,-0.5) M3(-8.5,-0.5) M4(-7.5,-0.5) M5(-6.5,-0.5) M6(-5.5,-0.5) M7(-4.5,-0.5) M9(-2.5,-0.5) M10(-1.5,-0.5) M11(-0.5,-0.5) M12(0.5,-0.5) M13(1.5,-0.5) M14(2.5,-0.5) M16(4.5,-0.5) M17(5.5,-0.5) M18(6.5,-0.5) M19(7.5,-0.5) M20(8.5,-0.5) M21(9.5,-0.5) M22(10.5,-0.5) N1(-10.5,-1.5) N2(-9.5,-1.5) N3(-8.5,-1.5) N4(-7.5,-1.5) N5(-6.5,-1.5) N6(-5.5,-1.5) N7(-4.5,-1.5) N9(-2.5,-1.5) N10(-1.5,-1.5) N11(-0.5,-1.5) N12(0.5,-1.5) N13(1.5,-1.5) N14(2.5,-1.5) N16(4.5,-1.5) N17(5.5,-1.5) N18(6.5,-1.5) N19(7.5,-1.5) N20(8.5,-1.5) N21(9.5,-1.5) N22(10.5,-1.5) P1(-10.5,-2.5) P2(-9.5,-2.5) P3(-8.5,-2.5) P4(-7.5,-2.5) P5(-6.5,-2.5) P6(-5.5,-2.5) P7(-4.5,-2.5) P9(-2.5,-2.5) P10(-1.5,-2.5) P11(-0.5,-2.5) P12(0.5,-2.5) P13(1.5,-2.5) P14(2.5,-2.5) P16(4.5,-2.5) P17(5.5,-2.5) P18(6.5,-2.5) P19(7.5,-2.5) P20(8.5,-2.5) P21(9.5,-2.5) P22(10.5,-2.5) R1(-10.5,-3.5) R2(-9.5,-3.5) R3(-8.5,-3.5) R4(-7.5,-3.5) R5(-6.5,-3.5) R6(-5.5,-3.5) R7(-4.5,-3.5) R16(4.5,-3.5) R17(5.5,-3.5) R18(6.5,-3.5) R19(7.5,-3.5) R20(8.5,-3.5) R21(9.5,-3.5) R22(10.5,-3.5) T1(-10.5,-4.5) T2(-9.5,-4.5) T3(-8.5,-4.5) T4(-7.5,-4.5) T5(-6.5,-4.5) T6(-5.5,-4.5) T7(-4.5,-4.5) T8(-3.5,-4.5) T9(-2.5,-4.5) T10(-1.5,-4.5) T11(-0.5,-4.5) T12(0.5,-4.5) T13(1.5,-4.5) T14(2.5,-4.5) T15(3.5,-4.5) T16(4.5,-4.5) T17(5.5,-4.5) T18(6.5,-4.5) T19(7.5,-4.5) T20(8.5,-4.5) T21(9.5,-4.5) T22(10.5,-4.5) U1(-10.5,-5.5) U2(-9.5,-5.5) U3(-8.5,-5.5) U4(-7.5,-5.5) U5(-6.5,-5.5) U6(-5.5,-5.5) U7(-4.5,-5.5) U8(-3.5,-5.5) U9(-2.5,-5.5) U10(-1.5,-5.5) U11(-0.5,-5.5) U12(0.5,-5.5) U13(1.5,-5.5) U14(2.5,-5.5) U15(3.5,-5.5) U16(4.5,-5.5) U17(5.5,-5.5) U18(6.5,-5.5) U19(7.5,-5.5) U20(8.5,-5.5) U21(9.5,-5.5) U22(10.5,-5.5) V1(-10.5,-6.5) V2(-9.5,-6.5) V3(-8.5,-6.5) V4(-7.5,-6.5) V5(-6.5,-6.5) V6(-5.5,-6.5) V7(-4.5,-6.5) V8(-3.5,-6.5) V9(-2.5,-6.5) V10(-1.5,-6.5) V11(-0.5,-6.5) V12(0.5,-6.5) V13(1.5,-6.5) V14(2.5,-6.5) V15(3.5,-6.5) V16(4.5,-6.5) V17(5.5,-6.5) V18(6.5,-6.5) V19(7.5,-6.5) V20(8.5,-6.5) V21(9.5,-6.5) V22(10.5,-6.5) W1(-10.5,-7.5) W2(-9.5,-7.5) W3(-8.5,-7.5) W4(-7.5,-7.5) W5(-6.5,-7.5) W6(-5.5,-7.5) W7(-4.5,-7.5) W8(-3.5,-7.5) W9(-2.5,-7.5) W10(-1.5,-7.5) W11(-0.5,-7.5) W12(0.5,-7.5) W13(1.5,-7.5) W14(2.5,-7.5) W15(3.5,-7.5) W16(4.5,-7.5) W17(5.5,-7.5) W18(6.5,-7.5) W19(7.5,-7.5) W20(8.5,-7.5) W21(9.5,-7.5) W22(10.5,-7.5) Y1(-10.5,-8.5) Y2(-9.5,-8.5) Y3(-8.5,-8.5) Y4(-7.5,-8.5) Y5(-6.5,-8.5) Y6(-5.5,-8.5) Y7(-4.5,-8.5) Y8(-3.5,-8.5) Y9(-2.5,-8.5) Y10(-1.5,-8.5) Y11(-0.5,-8.5) Y12(0.5,-8.5) Y13(1.5,-8.5) Y14(2.5,-8.5) Y15(3.5,-8.5) Y16(4.5,-8.5) Y17(5.5,-8.5) Y18(6.5,-8.5) Y19(7.5,-8.5) Y20(8.5,-8.5) Y21(9.5,-8.5) Y22(10.5,-8.5)
Top Overlay:
  circle w0.25: c-12.15,10.5 r0.125
  region: -10.5,11.5 -11.5,10.5 -11.5,11.5
  lines w0.2: -11.5,10.5 -10.5,11.5 ; -11.5,-11.5 11.5,-11.5 11.5,11.5 -11.5,11.5 -11.5,-11.5
Mechanical 13:
  lines w0.1: -11.5,-11.5 11.5,-11.5 11.5,11.5 -11.5,11.5 -11.5,-11.5
Mechanical 15:
  lines w0.1: -0.5,0 0.5,0 ; 0,-0.5 0,0.5 ; -12.5,-12.5 12.5,-12.5 12.5,12.5 -12.5,12.5 -12.5,-12.5
3D body: height 0, standoff 0, extent -11.5,-11.5 11.5,11.5

## BGA100P22X22-484 [mm] "BGA, 484-Leads, Body 23x23mm, Pitch 1mm"
height 2.44
pads (484):
  round 0.5 smd: A1(-10.5,10.5) A2(-9.5,10.5) A3(-8.5,10.5) A4(-7.5,10.5) A5(-6.5,10.5) A6(-5.5,10.5) A7(-4.5,10.5) A8(-3.5,10.5) A9(-2.5,10.5) A10(-1.5,10.5) A11(-0.5,10.5) A12(0.5,10.5) A13(1.5,10.5) A14(2.5,10.5) A15(3.5,10.5) A16(4.5,10.5) A17(5.5,10.5) A18(6.5,10.5) A19(7.5,10.5) A20(8.5,10.5) A21(9.5,10.5) A22(10.5,10.5) AA1(-10.5,-9.5) AA2(-9.5,-9.5) AA3(-8.5,-9.5) AA4(-7.5,-9.5) AA5(-6.5,-9.5) AA6(-5.5,-9.5) AA7(-4.5,-9.5) AA8(-3.5,-9.5) AA9(-2.5,-9.5) AA10(-1.5,-9.5) AA11(-0.5,-9.5) AA12(0.5,-9.5) AA13(1.5,-9.5) AA14(2.5,-9.5) AA15(3.5,-9.5) AA16(4.5,-9.5) AA17(5.5,-9.5) AA18(6.5,-9.5) AA19(7.5,-9.5) AA20(8.5,-9.5) AA21(9.5,-9.5) AA22(10.5,-9.5) AB1(-10.5,-10.5) AB2(-9.5,-10.5) AB3(-8.5,-10.5) AB4(-7.5,-10.5) AB5(-6.5,-10.5) AB6(-5.5,-10.5) AB7(-4.5,-10.5) AB8(-3.5,-10.5) AB9(-2.5,-10.5) AB10(-1.5,-10.5) AB11(-0.5,-10.5) AB12(0.5,-10.5) AB13(1.5,-10.5) AB14(2.5,-10.5) AB15(3.5,-10.5) AB16(4.5,-10.5) AB17(5.5,-10.5) AB18(6.5,-10.5) AB19(7.5,-10.5) AB20(8.5,-10.5) AB21(9.5,-10.5) AB22(10.5,-10.5) B1(-10.5,9.5) B2(-9.5,9.5) B3(-8.5,9.5) B4(-7.5,9.5) B5(-6.5,9.5) B6(-5.5,9.5) B7(-4.5,9.5) B8(-3.5,9.5) B9(-2.5,9.5) B10(-1.5,9.5) B11(-0.5,9.5) B12(0.5,9.5) B13(1.5,9.5) B14(2.5,9.5) B15(3.5,9.5) B16(4.5,9.5) B17(5.5,9.5) B18(6.5,9.5) B19(7.5,9.5) B20(8.5,9.5) B21(9.5,9.5) B22(10.5,9.5) C1(-10.5,8.5) C2(-9.5,8.5) C3(-8.5,8.5) C4(-7.5,8.5) C5(-6.5,8.5) C6(-5.5,8.5) C7(-4.5,8.5) C8(-3.5,8.5) C9(-2.5,8.5) C10(-1.5,8.5) C11(-0.5,8.5) C12(0.5,8.5) C13(1.5,8.5) C14(2.5,8.5) C15(3.5,8.5) C16(4.5,8.5) C17(5.5,8.5) C18(6.5,8.5) C19(7.5,8.5) C20(8.5,8.5) C21(9.5,8.5) C22(10.5,8.5) D1(-10.5,7.5) D2(-9.5,7.5) D3(-8.5,7.5) D4(-7.5,7.5) D5(-6.5,7.5) D6(-5.5,7.5) D7(-4.5,7.5) D8(-3.5,7.5) D9(-2.5,7.5) D10(-1.5,7.5) D11(-0.5,7.5) D12(0.5,7.5) D13(1.5,7.5) D14(2.5,7.5) D15(3.5,7.5) D16(4.5,7.5) D17(5.5,7.5) D18(6.5,7.5) D19(7.5,7.5) D20(8.5,7.5) D21(9.5,7.5) D22(10.5,7.5) E1(-10.5,6.5) E2(-9.5,6.5) E3(-8.5,6.5) E4(-7.5,6.5) E5(-6.5,6.5) E6(-5.5,6.5) E7(-4.5,6.5) E8(-3.5,6.5) E9(-2.5,6.5) E10(-1.5,6.5) E11(-0.5,6.5) E12(0.5,6.5) E13(1.5,6.5) E14(2.5,6.5) E15(3.5,6.5) E16(4.5,6.5) E17(5.5,6.5) E18(6.5,6.5) E19(7.5,6.5) E20(8.5,6.5) E21(9.5,6.5) E22(10.5,6.5) F1(-10.5,5.5) F2(-9.5,5.5) F3(-8.5,5.5) F4(-7.5,5.5) F5(-6.5,5.5) F6(-5.5,5.5) F7(-4.5,5.5) F8(-3.5,5.5) F9(-2.5,5.5) F10(-1.5,5.5) F11(-0.5,5.5) F12(0.5,5.5) F13(1.5,5.5) F14(2.5,5.5) F15(3.5,5.5) F16(4.5,5.5) F17(5.5,5.5) F18(6.5,5.5) F19(7.5,5.5) F20(8.5,5.5) F21(9.5,5.5) F22(10.5,5.5) G1(-10.5,4.5) G2(-9.5,4.5) G3(-8.5,4.5) G4(-7.5,4.5) G5(-6.5,4.5) G6(-5.5,4.5) G7(-4.5,4.5) G8(-3.5,4.5) G9(-2.5,4.5) G10(-1.5,4.5) G11(-0.5,4.5) G12(0.5,4.5) G13(1.5,4.5) G14(2.5,4.5) G15(3.5,4.5) G16(4.5,4.5) G17(5.5,4.5) G18(6.5,4.5) G19(7.5,4.5) G20(8.5,4.5) G21(9.5,4.5) G22(10.5,4.5) H1(-10.5,3.5) H2(-9.5,3.5) H3(-8.5,3.5) H4(-7.5,3.5) H5(-6.5,3.5) H6(-5.5,3.5) H7(-4.5,3.5) H8(-3.5,3.5) H9(-2.5,3.5) H10(-1.5,3.5) H11(-0.5,3.5) H12(0.5,3.5) H13(1.5,3.5) H14(2.5,3.5) H15(3.5,3.5) H16(4.5,3.5) H17(5.5,3.5) H18(6.5,3.5) H19(7.5,3.5) H20(8.5,3.5) H21(9.5,3.5) H22(10.5,3.5) J1(-10.5,2.5) J2(-9.5,2.5) J3(-8.5,2.5) J4(-7.5,2.5) J5(-6.5,2.5) J6(-5.5,2.5) J7(-4.5,2.5) J8(-3.5,2.5) J9(-2.5,2.5) J10(-1.5,2.5) J11(-0.5,2.5) J12(0.5,2.5) J13(1.5,2.5) J14(2.5,2.5) J15(3.5,2.5) J16(4.5,2.5) J17(5.5,2.5) J18(6.5,2.5) J19(7.5,2.5) J20(8.5,2.5) J21(9.5,2.5) J22(10.5,2.5) K1(-10.5,1.5) K2(-9.5,1.5) K3(-8.5,1.5) K4(-7.5,1.5) K5(-6.5,1.5) K6(-5.5,1.5) K7(-4.5,1.5) K8(-3.5,1.5) K9(-2.5,1.5) K10(-1.5,1.5) K11(-0.5,1.5) K12(0.5,1.5) K13(1.5,1.5) K14(2.5,1.5) K15(3.5,1.5) K16(4.5,1.5) K17(5.5,1.5) K18(6.5,1.5) K19(7.5,1.5) K20(8.5,1.5) K21(9.5,1.5) K22(10.5,1.5) L1(-10.5,0.5) L2(-9.5,0.5) L3(-8.5,0.5) L4(-7.5,0.5) L5(-6.5,0.5) L6(-5.5,0.5) L7(-4.5,0.5) L8(-3.5,0.5) L9(-2.5,0.5) L10(-1.5,0.5) L11(-0.5,0.5) L12(0.5,0.5) L13(1.5,0.5) L14(2.5,0.5) L15(3.5,0.5) L16(4.5,0.5) L17(5.5,0.5) L18(6.5,0.5) L19(7.5,0.5) L20(8.5,0.5) L21(9.5,0.5) L22(10.5,0.5) M1(-10.5,-0.5) M2(-9.5,-0.5) M3(-8.5,-0.5) M4(-7.5,-0.5) M5(-6.5,-0.5) M6(-5.5,-0.5) M7(-4.5,-0.5) M8(-3.5,-0.5) M9(-2.5,-0.5) M10(-1.5,-0.5) M11(-0.5,-0.5) M12(0.5,-0.5) M13(1.5,-0.5) M14(2.5,-0.5) M15(3.5,-0.5) M16(4.5,-0.5) M17(5.5,-0.5) M18(6.5,-0.5) M19(7.5,-0.5) M20(8.5,-0.5) M21(9.5,-0.5) M22(10.5,-0.5) N1(-10.5,-1.5) N2(-9.5,-1.5) N3(-8.5,-1.5) N4(-7.5,-1.5) N5(-6.5,-1.5) N6(-5.5,-1.5) N7(-4.5,-1.5) N8(-3.5,-1.5) N9(-2.5,-1.5) N10(-1.5,-1.5) N11(-0.5,-1.5) N12(0.5,-1.5) N13(1.5,-1.5) N14(2.5,-1.5) N15(3.5,-1.5) N16(4.5,-1.5) N17(5.5,-1.5) N18(6.5,-1.5) N19(7.5,-1.5) N20(8.5,-1.5) N21(9.5,-1.5) N22(10.5,-1.5) P1(-10.5,-2.5) P2(-9.5,-2.5) P3(-8.5,-2.5) P4(-7.5,-2.5) P5(-6.5,-2.5) P6(-5.5,-2.5) P7(-4.5,-2.5) P8(-3.5,-2.5) P9(-2.5,-2.5) P10(-1.5,-2.5) P11(-0.5,-2.5) P12(0.5,-2.5) P13(1.5,-2.5) P14(2.5,-2.5) P15(3.5,-2.5) P16(4.5,-2.5) P17(5.5,-2.5) P18(6.5,-2.5) P19(7.5,-2.5) P20(8.5,-2.5) P21(9.5,-2.5) P22(10.5,-2.5) R1(-10.5,-3.5) R2(-9.5,-3.5) R3(-8.5,-3.5) R4(-7.5,-3.5) R5(-6.5,-3.5) R6(-5.5,-3.5) R7(-4.5,-3.5) R8(-3.5,-3.5) R9(-2.5,-3.5) R10(-1.5,-3.5) R11(-0.5,-3.5) R12(0.5,-3.5) R13(1.5,-3.5) R14(2.5,-3.5) R15(3.5,-3.5) R16(4.5,-3.5) R17(5.5,-3.5) R18(6.5,-3.5) R19(7.5,-3.5) R20(8.5,-3.5) R21(9.5,-3.5) R22(10.5,-3.5) T1(-10.5,-4.5) T2(-9.5,-4.5) T3(-8.5,-4.5) T4(-7.5,-4.5) T5(-6.5,-4.5) T6(-5.5,-4.5) T7(-4.5,-4.5) T8(-3.5,-4.5) T9(-2.5,-4.5) T10(-1.5,-4.5) T11(-0.5,-4.5) T12(0.5,-4.5) T13(1.5,-4.5) T14(2.5,-4.5) T15(3.5,-4.5) T16(4.5,-4.5) T17(5.5,-4.5) T18(6.5,-4.5) T19(7.5,-4.5) T20(8.5,-4.5) T21(9.5,-4.5) T22(10.5,-4.5) U1(-10.5,-5.5) U2(-9.5,-5.5) U3(-8.5,-5.5) U4(-7.5,-5.5) U5(-6.5,-5.5) U6(-5.5,-5.5) U7(-4.5,-5.5) U8(-3.5,-5.5) U9(-2.5,-5.5) U10(-1.5,-5.5) U11(-0.5,-5.5) U12(0.5,-5.5) U13(1.5,-5.5) U14(2.5,-5.5) U15(3.5,-5.5) U16(4.5,-5.5) U17(5.5,-5.5) U18(6.5,-5.5) U19(7.5,-5.5) U20(8.5,-5.5) U21(9.5,-5.5) U22(10.5,-5.5) V1(-10.5,-6.5) V2(-9.5,-6.5) V3(-8.5,-6.5) V4(-7.5,-6.5) V5(-6.5,-6.5) V6(-5.5,-6.5) V7(-4.5,-6.5) V8(-3.5,-6.5) V9(-2.5,-6.5) V10(-1.5,-6.5) V11(-0.5,-6.5) V12(0.5,-6.5) V13(1.5,-6.5) V14(2.5,-6.5) V15(3.5,-6.5) V16(4.5,-6.5) V17(5.5,-6.5) V18(6.5,-6.5) V19(7.5,-6.5) V20(8.5,-6.5) V21(9.5,-6.5) V22(10.5,-6.5) W1(-10.5,-7.5) W2(-9.5,-7.5) W3(-8.5,-7.5) W4(-7.5,-7.5) W5(-6.5,-7.5) W6(-5.5,-7.5) W7(-4.5,-7.5) W8(-3.5,-7.5) W9(-2.5,-7.5) W10(-1.5,-7.5) W11(-0.5,-7.5) W12(0.5,-7.5) W13(1.5,-7.5) W14(2.5,-7.5) W15(3.5,-7.5) W16(4.5,-7.5) W17(5.5,-7.5) W18(6.5,-7.5) W19(7.5,-7.5) W20(8.5,-7.5) W21(9.5,-7.5) W22(10.5,-7.5) Y1(-10.5,-8.5) Y2(-9.5,-8.5) Y3(-8.5,-8.5) Y4(-7.5,-8.5) Y5(-6.5,-8.5) Y6(-5.5,-8.5) Y7(-4.5,-8.5) Y8(-3.5,-8.5) Y9(-2.5,-8.5) Y10(-1.5,-8.5) Y11(-0.5,-8.5) Y12(0.5,-8.5) Y13(1.5,-8.5) Y14(2.5,-8.5) Y15(3.5,-8.5) Y16(4.5,-8.5) Y17(5.5,-8.5) Y18(6.5,-8.5) Y19(7.5,-8.5) Y20(8.5,-8.5) Y21(9.5,-8.5) Y22(10.5,-8.5)
Top Overlay:
  circle w0.25: c-12.15,10.5 r0.125
  region: -10.5,11.5 -11.5,10.5 -11.5,11.5
  lines w0.2: -11.5,10.5 -10.5,11.5 ; -11.5,-11.5 -11.5,11.5 11.5,11.5 11.5,-11.5 -11.5,-11.5
Mechanical 13:
  lines w0.1: -11.5,-11.5 -11.5,11.5 11.5,11.5 11.5,-11.5 -11.5,-11.5
Mechanical 15:
  lines w0.1: -0.5,0 0.5,0 ; 0,-0.5 0,0.5 ; -12.5,-12.5 -12.5,12.5 12.5,12.5 12.5,-12.5 -12.5,-12.5
3D body: height 0, standoff 0, extent -11.5,-11.5 11.5,11.5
